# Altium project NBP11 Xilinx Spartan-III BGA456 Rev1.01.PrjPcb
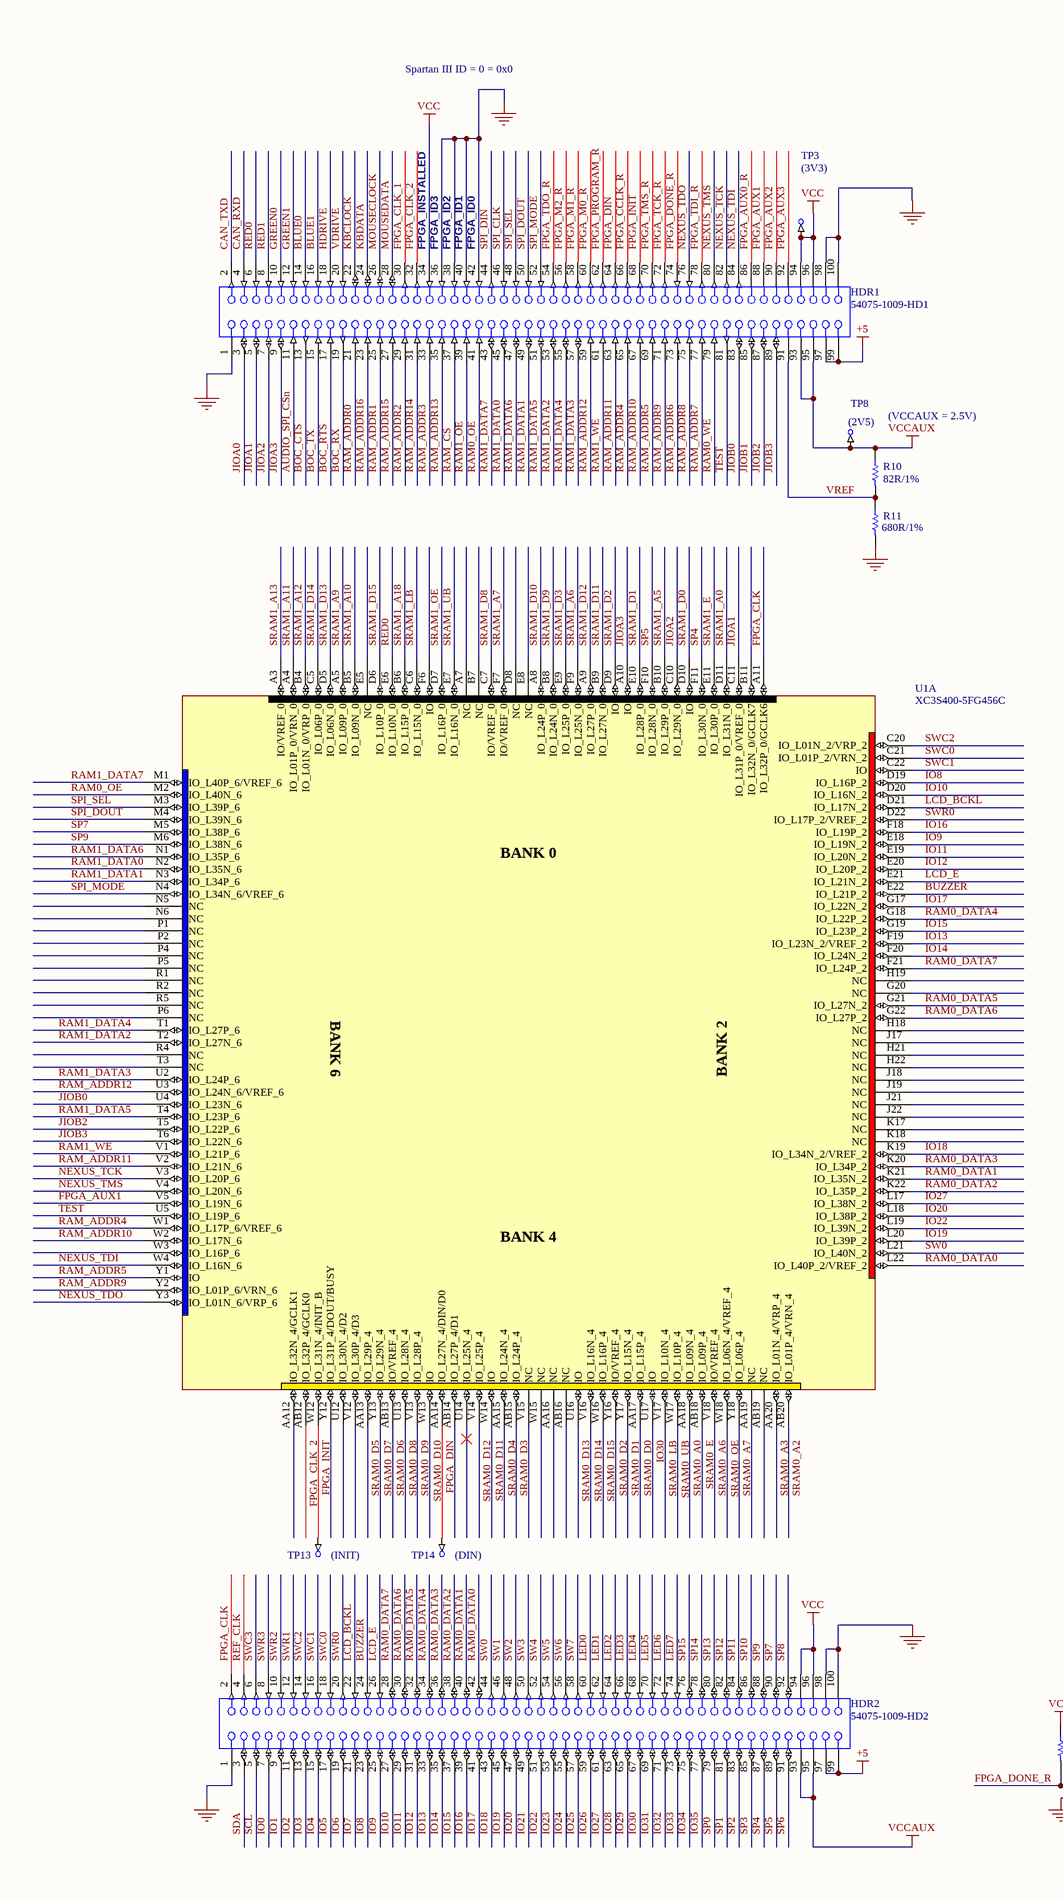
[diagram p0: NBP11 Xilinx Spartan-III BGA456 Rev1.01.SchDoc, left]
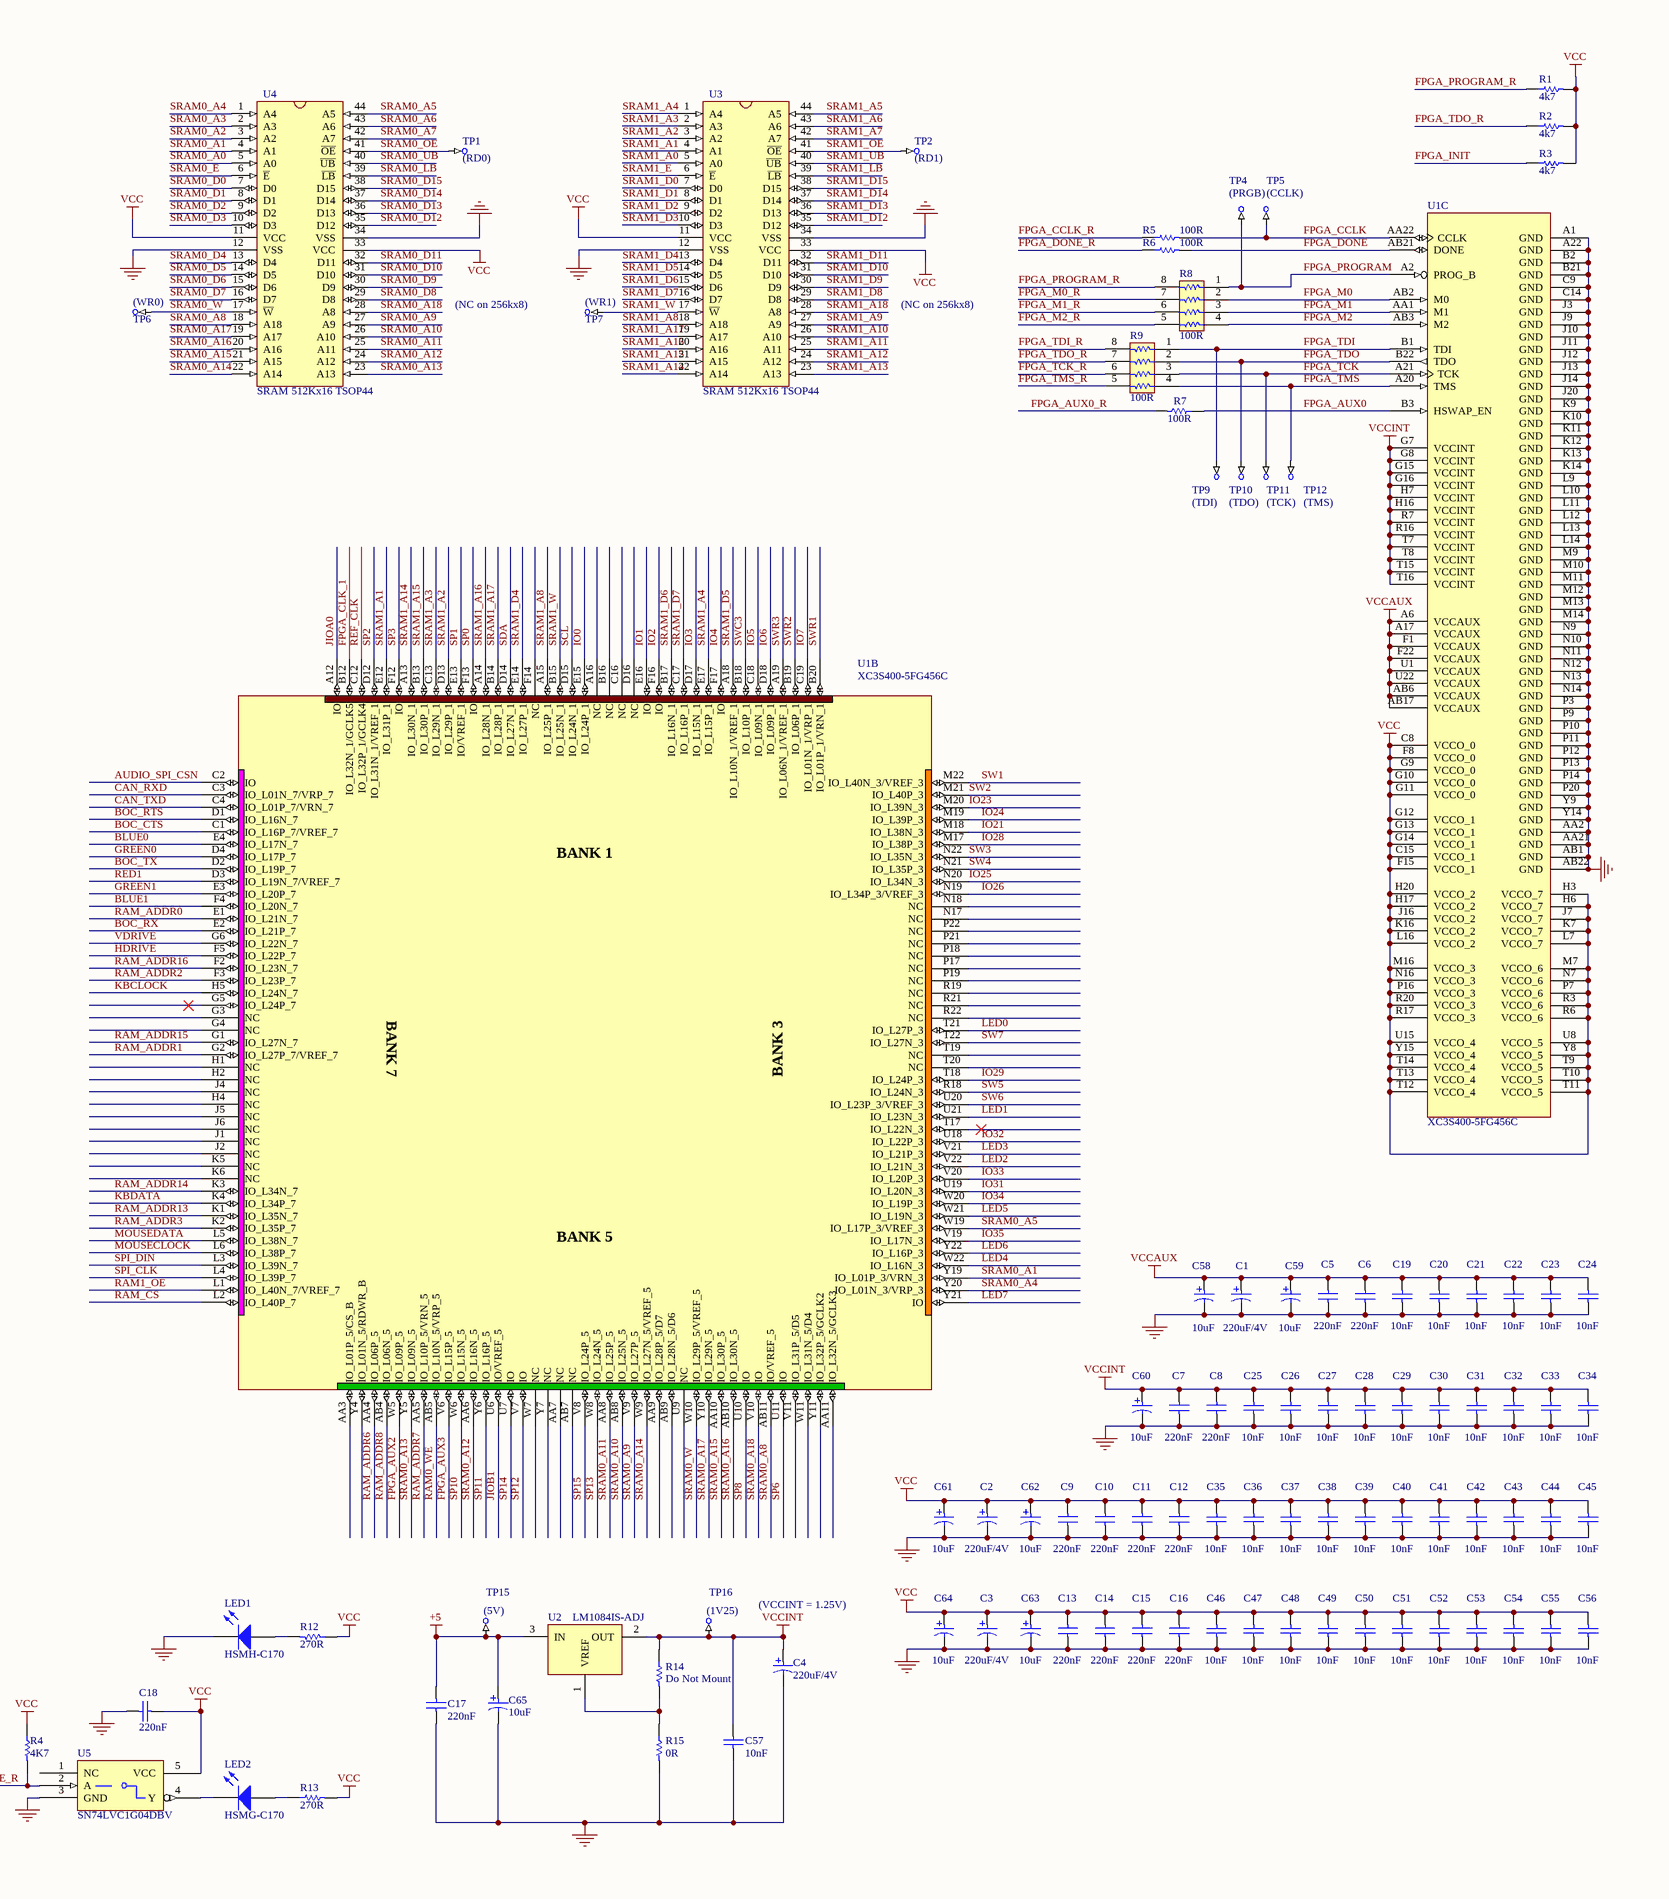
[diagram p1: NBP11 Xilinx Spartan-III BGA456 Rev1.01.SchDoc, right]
1 sheet, 105 parts. Net scope: global (net labels, ports and power ports of the same name join across sheets).
Board file: NBP11 Xilinx Spartan-III BGA456 Rev1.01.PcbDoc

## Sheet NBP11 Xilinx Spartan-III BGA456 Rev1.01.SchDoc: Spartan III BGA456 Daughterboard
size A2; Author: Ch.W.; Organization: Altium Limited; Address1: L3, 12a Rodborough Rd; Address2: Frenchs Forest; Address3: NSW; Address4: Australia 2086; DocumentNumber: 1; Revision: 1.01; SheetNumber: 1; SheetTotal: 1

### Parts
C1  220uF/4V  [MCCT-D]
C2  220uF/4V  [MCCT-D]
C3  220uF/4V  [MCCT-D]
C4  220uF/4V  [MCCT-D]
C5  220nF  [CC1608-0603]
C6  220nF  [CC1608-0603]
C7  220nF  [CC1608-0603]
C8  220nF  [CC1608-0603]
C9  220nF  [CC1608-0603]
C10  220nF  [CC1608-0603]
C11  220nF  [CC1608-0603]
C12  220nF  [CC1608-0603]
C13  220nF  [CC1608-0603]
C14  220nF  [CC1608-0603]
C15  220nF  [CC1608-0603]
C16  220nF  [CC1608-0603]
C17  220nF  [CC1608-0603]
C18  220nF  [CC1608-0603]
C19  10nF  [CC1608-0603]
C20  10nF  [CC1608-0603]
C21  10nF  [CC1608-0603]
C22  10nF  [CC1608-0603]
C23  10nF  [CC1608-0603]
C24  10nF  [CC1608-0603]
C25  10nF  [CC1608-0603]
C26  10nF  [CC1608-0603]
C27  10nF  [CC1608-0603]
C28  10nF  [CC1608-0603]
C29  10nF  [CC1608-0603]
C30  10nF  [CC1608-0603]
C31  10nF  [CC1608-0603]
C32  10nF  [CC1608-0603]
C33  10nF  [CC1608-0603]
C34  10nF  [CC1608-0603]
C35  10nF  [CC1608-0603]
C36  10nF  [CC1608-0603]
C37  10nF  [CC1608-0603]
C38  10nF  [CC1608-0603]
C39  10nF  [CC1608-0603]
C40  10nF  [CC1608-0603]
C41  10nF  [CC1608-0603]
C42  10nF  [CC1608-0603]
C43  10nF  [CC1608-0603]
C44  10nF  [CC1608-0603]
C45  10nF  [CC1608-0603]
C46  10nF  [CC1608-0603]
C47  10nF  [CC1608-0603]
C48  10nF  [CC1608-0603]
C49  10nF  [CC1608-0603]
C50  10nF  [CC1608-0603]
C51  10nF  [CC1608-0603]
C52  10nF  [CC1608-0603]
C53  10nF  [CC1608-0603]
C54  10nF  [CC1608-0603]
C55  10nF  [CC1608-0603]
C56  10nF  [CC1608-0603]
C57  10nF  [CC1608-0603]
C58  10uF  [MCCT-B]
C59  10uF  [MCCT-B]
C60  10uF  [MCCT-B]
C61  10uF  [MCCT-B]
C62  10uF  [MCCT-B]
C63  10uF  [MCCT-B]
C64  10uF  [MCCT-B]
C65  10uF  [MCCT-B]
HDR1  54075-1009-HD1  [54075]
HDR2  54075-1009-HD2  [54075]
LED1  HSMH-C170  [SMD _LED]
LED2  HSMG-C170  [SMD _LED]
R1  4k7  [CR2012-0805]
R2  4k7  [CR2012-0805]
R3  4k7  [CR2012-0805]
R4  4K7  [CR2012-0805]
R5  100R  [CR2012-0805]
R6  100R  [CR2012-0805]
R7  100R  [CR2012-0805]
R8  100R  [MNR34]
R9  100R  [MNR34]
R10  82R/1%  [CR2012-0805]
R11  680R/1%  [CR2012-0805]
R12  270R  [CR2012-0805]
R13  270R  [CR2012-0805]
R14  Do Not Mount  [CR2012-0805]
R15  0R  [CR2012-0805]
TP1  (RD0)  [TestPin]  (no BOM)
TP2  (RD1)  [TestPin]  (no BOM)
TP3  (3V3)  [TestPin]  (no BOM)
TP4  (PRGB)  [TestPin]  (no BOM)
TP5  (CCLK)  [TestPin]  (no BOM)
TP6  (WR0)  [TestPin]  (no BOM)
TP7  (WR1)  [TestPin]  (no BOM)
TP8  (2V5)  [TestPin]  (no BOM)
TP9  (TDI)  [TestPin]  (no BOM)
TP10  (TDO)  [TestPin]  (no BOM)
TP11  (TCK)  [TestPin]  (no BOM)
TP12  (TMS)  [TestPin]  (no BOM)
TP13  (INIT)  [TestPin]  (no BOM)
TP14  (DIN)  [TestPin]  (no BOM)
TP15  (5V)  [TestPin]  (no BOM)
TP16  (1V25)  [TestPin]  (no BOM)
U1  XC3S400-5FG456C  [FG456]  (parts A,B,C of 3)
U2  LM1084IS-ADJ  [TO-263]
U3  SRAM 512Kx16 TSOP44  [SO-G44/P.8]
U4  SRAM 512Kx16 TSOP44  [SO-G44/P.8]
U5  SN74LVC1G04DBV  [SO-G5/P.95]

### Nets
+5: C17.1 C65.1 HDR1.97 HDR1.99 HDR2.97 HDR2.99 TP15.1 U2.3(IN)
GND: C1.2 C2.2 C3.2 C4.2 C5.2 C6.2 C7.2 C8.2 C9.2 C10.2 C11.2 C12.2 C13.2 C14.2 C15.2 C16.2 C17.2 C18.1 C19.2 C20.2 C21.2 C22.2 C23.2 C24.2 C25.2 C26.2 C27.2 C28.2 C29.2 C30.2 C31.2 C32.2 C33.2 C34.2 C35.2 C36.2 C37.2 C38.2 C39.2 C40.2 C41.2 C42.2 C43.2 C44.2 C45.2 C46.2 C47.2 C48.2 C49.2 C50.2 C51.2 C52.2 C53.2 C54.2 C55.2 C56.2 C57.2 C58.2 C59.2 C60.2 C61.2 C62.2 C63.2 C64.2 C65.2 HDR1.1 HDR1.36 HDR1.38 HDR1.40 HDR1.42 HDR1.98 HDR1.100 HDR2.1 HDR2.98 HDR2.100 LED1.2(K) R11.2 R15.2 U1.A1(GND) U1.A22(GND) U1.AA2(GND) U1.AA21(GND) U1.AB1(GND) U1.AB22(GND) U1.B2(GND) U1.B21(GND) U1.C9(GND) U1.C14(GND) U1.J3(GND) U1.J9(GND) U1.J10(GND) U1.J11(GND) U1.J12(GND) U1.J13(GND) U1.J14(GND) U1.J20(GND) U1.K9(GND) U1.K10(GND) U1.K11(GND) U1.K12(GND) U1.K13(GND) U1.K14(GND) U1.L9(GND) U1.L10(GND) U1.L11(GND) U1.L12(GND) U1.L13(GND) U1.L14(GND) U1.M9(GND) U1.M10(GND) U1.M11(GND) U1.M12(GND) U1.M13(GND) U1.M14(GND) U1.N9(GND) U1.N10(GND) U1.N11(GND) U1.N12(GND) U1.N13(GND) U1.N14(GND) U1.P3(GND) U1.P9(GND) U1.P10(GND) U1.P11(GND) U1.P12(GND) U1.P13(GND) U1.P14(GND) U1.P20(GND) U1.Y9(GND) U1.Y14(GND) U3.12(VSS) U3.34(VSS) U4.12(VSS) U4.34(VSS) U5.3(GND)
VCC: C2.1 C3.1 C9.1 C10.1 C11.1 C12.1 C13.1 C14.1 C15.1 C16.1 C18.2 C35.1 C36.1 C37.1 C38.1 C39.1 C40.1 C41.1 C42.1 C43.1 C44.1 C45.1 C46.1 C47.1 C48.1 C49.1 C50.1 C51.1 C52.1 C53.1 C54.1 C55.1 C56.1 C61.1 C62.1 C63.1 C64.1 HDR1.34 HDR1.94 HDR1.96 HDR2.94 HDR2.96 R1.2 R2.2 R3.2 R4.1 R12.1 R13.2 TP3.1 U1.C8(VCCO_0) U1.C15(VCCO_1) U1.F8(VCCO_0) U1.F15(VCCO_1) U1.G9(VCCO_0) U1.G10(VCCO_0) U1.G11(VCCO_0) U1.G12(VCCO_1) U1.G13(VCCO_1) U1.G14(VCCO_1) U1.H3(VCCO_7) U1.H6(VCCO_7) U1.H17(VCCO_2) U1.H20(VCCO_2) U1.J7(VCCO_7) U1.J16(VCCO_2) U1.K7(VCCO_7) U1.K16(VCCO_2) U1.L7(VCCO_7) U1.L16(VCCO_2) U1.M7(VCCO_6) U1.M16(VCCO_3) U1.N7(VCCO_6) U1.N16(VCCO_3) U1.P7(VCCO_6) U1.P16(VCCO_3) U1.R3(VCCO_6) U1.R6(VCCO_6) U1.R17(VCCO_3) U1.R20(VCCO_3) U1.T9(VCCO_5) U1.T10(VCCO_5) U1.T11(VCCO_5) U1.T12(VCCO_4) U1.T13(VCCO_4) U1.T14(VCCO_4) U1.U8(VCCO_5) U1.U15(VCCO_4) U1.Y8(VCCO_5) U1.Y15(VCCO_4) U3.11(VCC) U3.33(VCC) U4.11(VCC) U4.33(VCC) U5.5(VCC)
VCCAUX: C1.1 C5.1 C6.1 C19.1 C20.1 C21.1 C22.1 C23.1 C24.1 C58.1 C59.1 HDR1.93 HDR1.95 HDR2.93 HDR2.95 R10.1 TP8.1 U1.A6(VCCAUX) U1.A17(VCCAUX) U1.AB6(VCCAUX) U1.AB17(VCCAUX) U1.F1(VCCAUX) U1.F22(VCCAUX) U1.U1(VCCAUX) U1.U22(VCCAUX)
VCCINT: C4.1 C7.1 C8.1 C25.1 C26.1 C27.1 C28.1 C29.1 C30.1 C31.1 C32.1 C33.1 C34.1 C57.1 C60.1 R14.1 TP16.1 U1.G7(VCCINT) U1.G8(VCCINT) U1.G15(VCCINT) U1.G16(VCCINT) U1.H7(VCCINT) U1.H16(VCCINT) U1.R7(VCCINT) U1.R16(VCCINT) U1.T7(VCCINT) U1.T8(VCCINT) U1.T15(VCCINT) U1.T16(VCCINT) U2.2(OUT)
AUDIO_SPI_CSn: HDR1.11 U1.C2(IO)
BLUE0: HDR1.14 U1.E4(IO_L17N_7)
BLUE1: HDR1.16 U1.F4(IO_L20N_7)
BOC_CTS: HDR1.13 U1.C1(IO_L16P_7/VREF_7)
BOC_RTS: HDR1.17 U1.D1(IO_L16N_7)
BOC_RX: HDR1.19 U1.E2(IO_L21P_7)
BOC_TX: HDR1.15 U1.D2(IO_L19P_7)
BUZZER: HDR2.24 U1.E22(IO_L21P_2)
CAN_RXD: HDR1.4 U1.C3(IO_L01N_7/VRP_7)
CAN_TXD: HDR1.2 U1.C4(IO_L01P_7/VRN_7)
FPGA_AUX0: R7.1 U1.B3(HSWAP_EN)
FPGA_AUX0_R: HDR1.86 R7.2
FPGA_AUX1: HDR1.88 U1.V5(IO_L19N_6)
FPGA_AUX2: HDR1.90 U1.W5(IO_L09P_5)
FPGA_AUX3: HDR1.92 U1.V6(IO_L15P_5)
FPGA_CCLK: R5.2 TP5.1 U1.AA22(CCLK)
FPGA_CCLK_R: HDR1.66 R5.1
FPGA_CLK: HDR2.2 U1.A11(IO_L32P_0/GCLK6)
FPGA_CLK_1: HDR1.30 U1.B12(IO_L32N_1/GCLK5)
FPGA_CLK_2: HDR1.32 U1.AB12(IO_L32P_4/GCLK0)
FPGA_DIN: HDR1.64 TP14.1 U1.AA14(IO_L27N_4/DIN/D0)
FPGA_DONE: R6.2 U1.AB21(DONE)
FPGA_DONE_R: HDR1.74 R4.2 R6.1 U5.2(A)
FPGA_INIT: HDR1.68 R3.1 TP13.1 U1.W12(IO_L31N_4/INIT_B)
FPGA_M0: R8.2 U1.AB2(M0)
FPGA_M0_R: HDR1.60 R8.7
FPGA_M1: R8.3 U1.AA1(M1)
FPGA_M1_R: HDR1.58 R8.6
FPGA_M2: R8.4 U1.AB3(M2)
FPGA_M2_R: HDR1.56 R8.5
FPGA_PROGRAM: R8.1 TP4.1 U1.A2(PROG_B)
FPGA_PROGRAM_R: HDR1.62 R1.1 R8.8
FPGA_TCK: R9.3 TP11.1 U1.A21(TCK)
FPGA_TCK_R: HDR1.72 R9.6
FPGA_TDI: R9.1 TP9.1 U1.B1(TDI)
FPGA_TDI_R: HDR1.78 R9.8
FPGA_TDO: R9.2 TP10.1 U1.B22(TDO)
FPGA_TDO_R: HDR1.54 R2.1 R9.7
FPGA_TMS: R9.4 TP12.1 U1.A20(TMS)
FPGA_TMS_R: HDR1.70 R9.5
GREEN0: HDR1.10 U1.D4(IO_L17P_7)
GREEN1: HDR1.12 U1.E3(IO_L20P_7)
HDRIVE: HDR1.18 U1.F5(IO_L22P_7)
IO0: HDR2.7 U1.E15(IO_L24P_1)
IO1: HDR2.9 U1.E16(IO)
IO2: HDR2.11 U1.F16(IO)
IO3: HDR2.13 U1.D17(IO_L15N_1)
IO4: HDR2.15 U1.F17(IO)
IO5: HDR2.17 U1.C18(IO_L09N_1)
IO6: HDR2.19 U1.D18(IO_L09P_1)
IO7: HDR2.21 U1.C19(IO_L01N_1/VRP_1)
IO8: HDR2.23 U1.D19(IO_L16P_2)
IO9: HDR2.25 U1.E18(IO_L19N_2)
IO10: HDR2.27 U1.D20(IO_L16N_2)
IO11: HDR2.29 U1.E19(IO_L20N_2)
IO12: HDR2.31 U1.E20(IO_L20P_2)
IO13: HDR2.33 U1.F19(IO_L23N_2/VREF_2)
IO14: HDR2.35 U1.F20(IO_L24N_2)
IO15: HDR2.37 U1.G19(IO_L23P_2)
IO16: HDR2.39 U1.F18(IO_L19P_2)
IO17: HDR2.41 U1.G17(IO_L22N_2)
IO18: HDR2.43 U1.K19(IO_L34N_2/VREF_2)
IO19: HDR2.45 U1.L20(IO_L39P_2)
IO20: HDR2.47 U1.L18(IO_L38P_2)
IO21: HDR2.49 U1.M18(IO_L38N_3)
IO22: HDR2.51 U1.L19(IO_L39N_2)
IO23: HDR2.53 U1.M20(IO_L39N_3)
IO24: HDR2.55 U1.M19(IO_L39P_3)
IO25: HDR2.57 U1.N20(IO_L34N_3)
IO26: HDR2.59 U1.N19(IO_L34P_3/VREF_3)
IO27: HDR2.61 U1.L17(IO_L38N_2)
IO28: HDR2.63 U1.M17(IO_L38P_3)
IO29: HDR2.65 U1.T18(IO_L24P_3)
IO30: HDR2.67 U1.U17(IO)
IO31: HDR2.69 U1.U19(IO_L20N_3)
IO32: HDR2.71 U1.U18(IO_L22P_3)
IO33: HDR2.73 U1.V20(IO_L20P_3)
IO34: HDR2.75 U1.W20(IO_L19P_3)
IO35: HDR2.77 U1.V19(IO_L17N_3)
JIOA0: HDR1.3 U1.A12(IO)
JIOA1: HDR1.5 U1.C11(IO_L31P_0/VREF_0)
JIOA2: HDR1.7 U1.C10(IO_L29N_0)
JIOA3: HDR1.9 U1.A10(IO)
JIOB0: HDR1.83 U1.U4(IO_L23N_6)
JIOB1: HDR1.85 U1.U6(IO/VREF_5)
JIOB2: HDR1.87 U1.T5(IO_L22P_6)
JIOB3: HDR1.89 U1.T6(IO_L22N_6)
KBCLOCK: HDR1.22 U1.H5(IO_L24N_7)
KBDATA: HDR1.24 U1.K4(IO_L34P_7)
LCD_BCKL: HDR2.22 U1.D21(IO_L17N_2)
LCD_E: HDR2.26 U1.E21(IO_L21N_2)
LED0: HDR2.60 U1.T21(IO_L27P_3)
LED1: HDR2.62 U1.U21(IO_L23N_3)
LED2: HDR2.64 U1.V22(IO_L21N_3)
LED3: HDR2.66 U1.V21(IO_L21P_3)
LED4: HDR2.68 U1.W22(IO_L16N_3)
LED5: HDR2.70 U1.W21(IO_L19N_3)
LED6: HDR2.72 U1.Y22(IO_L16P_3)
LED7: HDR2.74 U1.Y21(IO)
MOUSECLOCK: HDR1.26 U1.L6(IO_L38P_7)
MOUSEDATA: HDR1.28 U1.L5(IO_L38N_7)
NEXUS_TCK: HDR1.82 U1.V3(IO_L20P_6)
NEXUS_TDI: HDR1.84 U1.W4(IO_L16N_6)
NEXUS_TDO: HDR1.76 U1.Y3(IO_L01N_6/VRP_6)
NEXUS_TMS: HDR1.80 U1.V4(IO_L20N_6)
RAM0_DATA0: HDR2.42 U1.L22(IO_L40P_2/VREF_2)
RAM0_DATA1: HDR2.40 U1.K21(IO_L35N_2)
RAM0_DATA2: HDR2.38 U1.K22(IO_L35P_2)
RAM0_DATA3: HDR2.36 U1.K20(IO_L34P_2)
RAM0_DATA4: HDR2.34 U1.G18(IO_L22P_2)
RAM0_DATA5: HDR2.32 U1.G21(IO_L27N_2)
RAM0_DATA6: HDR2.30 U1.G22(IO_L27P_2)
RAM0_DATA7: HDR2.28 U1.F21(IO_L24P_2)
RAM0_OE: HDR1.41 U1.M2(IO_L40N_6)
RAM0_WE: HDR1.79 U1.AB5(IO_L10N_5/VRP_5)
RAM1_DATA0: HDR1.45 U1.N2(IO_L35N_6)
RAM1_DATA1: HDR1.49 U1.N3(IO_L34P_6)
RAM1_DATA2: HDR1.53 U1.T2(IO_L27N_6)
RAM1_DATA3: HDR1.57 U1.U2(IO_L24P_6)
RAM1_DATA4: HDR1.55 U1.T1(IO_L27P_6)
RAM1_DATA5: HDR1.51 U1.T4(IO_L23P_6)
RAM1_DATA6: HDR1.47 U1.N1(IO_L35P_6)
RAM1_DATA7: HDR1.43 U1.M1(IO_L40P_6/VREF_6)
RAM1_OE: HDR1.39 U1.L1(IO_L40N_7/VREF_7)
RAM1_WE: HDR1.61 U1.V1(IO_L21P_6)
RAM_ADDR0: HDR1.21 U1.E1(IO_L21N_7)
RAM_ADDR1: HDR1.25 U1.G2(IO_L27P_7/VREF_7)
RAM_ADDR2: HDR1.29 U1.F3(IO_L23P_7)
RAM_ADDR3: HDR1.33 U1.K2(IO_L35P_7)
RAM_ADDR4: HDR1.65 U1.W1(IO_L17P_6/VREF_6)
RAM_ADDR5: HDR1.69 U1.Y1(IO)
RAM_ADDR6: HDR1.73 U1.AA4(IO_L06P_5)
RAM_ADDR7: HDR1.77 U1.AA5(IO_L10P_5/VRN_5)
RAM_ADDR8: HDR1.75 U1.AB4(IO_L06N_5)
RAM_ADDR9: HDR1.71 U1.Y2(IO_L01P_6/VRN_6)
RAM_ADDR10: HDR1.67 U1.W2(IO_L17N_6)
RAM_ADDR11: HDR1.63 U1.V2(IO_L21N_6)
RAM_ADDR12: HDR1.59 U1.U3(IO_L24N_6/VREF_6)
RAM_ADDR13: HDR1.35 U1.K1(IO_L35N_7)
RAM_ADDR14: HDR1.31 U1.K3(IO_L34N_7)
RAM_ADDR15: HDR1.27 U1.G1(IO_L27N_7)
RAM_ADDR16: HDR1.23 U1.F2(IO_L23N_7)
RAM_CS: HDR1.37 U1.L2(IO_L40P_7)
RED0: HDR1.6 U1.E6(IO_L10N_0)
RED1: HDR1.8 U1.D3(IO_L19N_7/VREF_7)
REF_CLK: HDR2.4 U1.C12(IO_L32P_1/GCLK4)
SCL: HDR2.5 U1.D15(IO_L24N_1)
SDA: HDR2.3 U1.D14(IO_L27N_1)
SP0: HDR2.79 U1.F13(IO)
SP1: HDR2.81 U1.E13(IO/VREF_1)
SP2: HDR2.83 U1.D12(IO_L31N_1/VREF_1)
SP3: HDR2.85 U1.F12(IO)
SP4: HDR2.87 U1.F11(IO_L30N_0)
SP5: HDR2.89 U1.F10(IO_L28N_0)
SP6: HDR2.91 U1.U11(IO)
SP7: HDR2.90 U1.M5(IO_L38P_6)
SP8: HDR2.92 U1.U10(IO)
SP9: HDR2.88 U1.M6(IO_L38N_6)
SP10: HDR2.86 U1.W6(IO_L15N_5)
SP11: HDR2.84 U1.Y6(IO_L16P_5)
SP12: HDR2.82 U1.V7(IO)
SP13: HDR2.80 U1.W8(IO_L24N_5)
SP14: HDR2.78 U1.U7(IO)
SP15: HDR2.76 U1.V8(IO_L24P_5)
SPI_CLK: HDR1.46 U1.L4(IO_L39P_7)
SPI_DIN: HDR1.44 U1.L3(IO_L39N_7)
SPI_DOUT: HDR1.50 U1.M4(IO_L39N_6)
SPI_MODE: HDR1.52 U1.N4(IO_L34N_6/VREF_6)
SPI_SEL: HDR1.48 U1.M3(IO_L39P_6)
SRAM0_A0: U1.AA18(IO_L09N_4) U3.5(A0)
SRAM0_A1: U1.Y19(IO_L01P_3/VRN_3) U3.4(A1)
SRAM0_A2: U1.AB20(IO_L01P_4/VRN_4) U3.3(A2)
SRAM0_A3: U1.AA20(IO_L01N_4/VRP_4) U3.2(A3)
SRAM0_A4: U1.Y20(IO_L01N_3/VRP_3) U3.1(A4)
SRAM0_A5: U1.W19(IO_L17P_3/VREF_3) U3.44(A5)
SRAM0_A6: U1.V18(IO/VREF_4) U3.43(A6)
SRAM0_A7: U1.Y18(IO_L06P_4) U3.42(A7)
SRAM0_A8: U1.AB11(IO/VREF_5) U3.18(A18)
SRAM0_A9: U1.V9(IO_L27P_5) U3.27(A9)
SRAM0_A10: U1.AB8(IO_L25N_5) U3.26(A10)
SRAM0_A11: U1.AA8(IO_L25P_5) U3.25(A11)
SRAM0_A12: U1.AA6(IO_L16N_5) U3.24(A12)
SRAM0_A13: U1.Y5(IO_L09N_5) U3.23(A13)
SRAM0_A14: U1.W9(IO_L27N_5/VREF_5) U3.22(A14)
SRAM0_A15: U1.AA10(IO_L30P_5) U3.21(A15)
SRAM0_A16: U1.AB10(IO_L30N_5) U3.20(A16)
SRAM0_A17: U1.Y10(IO_L29N_5) U3.19(A17)
SRAM0_A18: U1.V10(IO) U3.28(A8)
SRAM0_D0: U1.AA17(IO_L15P_4) U3.7(D0)
SRAM0_D1: U1.Y17(IO_L15N_4) U3.8(D1)
SRAM0_D2: U1.Y16(IO/VREF_4) U3.9(D2)
SRAM0_D3: U1.AB15(IO_L24P_4) U3.10(D3)
SRAM0_D4: U1.AA15(IO_L24N_4) U3.13(D4)
SRAM0_D5: U1.AA13(IO_L29P_4) U3.14(D5)
SRAM0_D6: U1.AB13(IO/VREF_4) U3.15(D6)
SRAM0_D7: U1.Y13(IO_L29N_4) U3.16(D7)
SRAM0_D8: U1.U13(IO_L28N_4) U3.29(D8)
SRAM0_D9: U1.V13(IO_L28P_4) U3.30(D9)
SRAM0_D10: U1.W13(IO) U3.31(D10)
SRAM0_D11: U1.W14(IO) U3.32(D11)
SRAM0_D12: U1.V14(IO_L25P_4) U3.35(D12)
SRAM0_D13: U1.U16(IO) U3.36(D13)
SRAM0_D14: U1.V16(IO_L16N_4) U3.37(D14)
SRAM0_D15: U1.W16(IO_L16P_4) U3.38(D15)
SRAM0_E: U1.AB18(IO_L09P_4) U3.6(~{E})
SRAM0_LB: U1.V17(IO_L10N_4) U3.39(~{LB})
SRAM0_OE: TP1.1 U1.W18(IO_L06N_4/VREF_4) U3.41(~{OE})
SRAM0_UB: U1.W17(IO_L10P_4) U3.40(~{UB})
SRAM0_W: TP6.1 U1.W10(IO_L29P_5/VREF_5) U3.17(~{W})
SRAM1_A0: U1.D11(IO_L31N_0) U4.5(A0)
SRAM1_A1: U1.E12(IO_L31P_1) U4.4(A1)
SRAM1_A2: U1.D13(IO_L29P_1) U4.3(A2)
SRAM1_A3: U1.C13(IO_L29N_1) U4.2(A3)
SRAM1_A4: U1.E17(IO_L15P_1) U4.1(A4)
SRAM1_A5: U1.B10(IO_L29P_0) U4.44(A5)
SRAM1_A6: U1.F9(IO_L25N_0) U4.43(A6)
SRAM1_A7: U1.F7(IO/VREF_0) U4.42(A7)
SRAM1_A8: U1.A15(IO_L25P_1) U4.18(A18)
SRAM1_A9: U1.A5(IO_L09P_0) U4.27(A9)
SRAM1_A10: U1.B5(IO_L09N_0) U4.26(A10)
SRAM1_A11: U1.A4(IO_L01P_0/VRN_0) U4.25(A11)
SRAM1_A12: U1.B4(IO_L01N_0/VRP_0) U4.24(A12)
SRAM1_A13: U1.A3(IO/VREF_0) U4.23(A13)
SRAM1_A14: U1.A13(IO_L30N_1) U4.22(A14)
SRAM1_A15: U1.B13(IO_L30P_1) U4.21(A15)
SRAM1_A16: U1.A14(IO_L28N_1) U4.20(A16)
SRAM1_A17: U1.B14(IO_L28P_1) U4.19(A17)
SRAM1_A18: U1.B6(IO_L15P_0) U4.28(A8)
SRAM1_D0: U1.D10(IO) U4.7(D0)
SRAM1_D1: U1.E10(IO_L28P_0) U4.8(D1)
SRAM1_D2: U1.D9(IO) U4.9(D2)
SRAM1_D3: U1.E9(IO_L25P_0) U4.10(D3)
SRAM1_D4: U1.E14(IO_L27P_1) U4.13(D4)
SRAM1_D5: U1.A18(IO_L10N_1/VREF_1) U4.14(D5)
SRAM1_D6: U1.B17(IO_L16N_1) U4.15(D6)
SRAM1_D7: U1.C17(IO_L16P_1) U4.16(D7)
SRAM1_D8: U1.C7(IO/VREF_0) U4.29(D8)
SRAM1_D9: U1.B8(IO_L24N_0) U4.30(D9)
SRAM1_D10: U1.A8(IO_L24P_0) U4.31(D10)
SRAM1_D11: U1.B9(IO_L27N_0) U4.32(D11)
SRAM1_D12: U1.A9(IO_L27P_0) U4.35(D12)
SRAM1_D13: U1.D5(IO_L06N_0) U4.36(D13)
SRAM1_D14: U1.C5(IO_L06P_0) U4.37(D14)
SRAM1_D15: U1.D6(IO_L10P_0) U4.38(D15)
SRAM1_E: U1.E11(IO_L30P_0) U4.6(~{E})
SRAM1_LB: U1.C6(IO_L15N_0) U4.39(~{LB})
SRAM1_OE: TP2.1 U1.D7(IO_L16P_0) U4.41(~{OE})
SRAM1_UB: U1.E7(IO_L16N_0) U4.40(~{UB})
SRAM1_W: TP7.1 U1.B15(IO_L25N_1) U4.17(~{W})
SW0: HDR2.44 U1.L21(IO_L40N_2)
SW1: HDR2.46 U1.M22(IO_L40N_3/VREF_3)
SW2: HDR2.48 U1.M21(IO_L40P_3)
SW3: HDR2.50 U1.N22(IO_L35N_3)
SW4: HDR2.52 U1.N21(IO_L35P_3)
SW5: HDR2.54 U1.R18(IO_L24N_3)
SW6: HDR2.56 U1.U20(IO_L23P_3/VREF_3)
SW7: HDR2.58 U1.T22(IO_L27N_3)
SWC0: HDR2.18 U1.C21(IO_L01P_2/VRN_2)
SWC1: HDR2.16 U1.C22(IO)
SWC2: HDR2.14 U1.C20(IO_L01N_2/VRP_2)
SWC3: HDR2.6 U1.B18(IO_L10P_1)
SWR0: HDR2.20 U1.D22(IO_L17P_2/VREF_2)
SWR1: HDR2.12 U1.B20(IO_L01P_1/VRN_1)
SWR2: HDR2.10 U1.B19(IO_L06P_1)
SWR3: HDR2.8 U1.A19(IO_L06N_1/VREF_1)
TEST: HDR1.81 U1.U5(IO_L19P_6)
VDRIVE: HDR1.20 U1.G6(IO_L22N_7)
VREF: HDR1.91 R10.2 R11.1
NetLED1_1: LED1.1(A) R12.2
NetLED2_1: LED2.1(A) R13.1
NetLED2_2: LED2.2(K) U5.4(Y)
NetR14_2: R14.2 R15.1 U2.1(VREF)

Not connected (* = marked no-connect by the designer): U1 A7(NC) A16(NC) AA3(IO_L01P_5/CS_B) AA7(NC) AA9(IO_L28P_5/D7) AA11(IO_L32N_5/GCLK3) AA12(IO_L32N_4/GCLK1) AA16(NC) AA19(NC) AB7(NC) AB9(IO_L28N_5/D6) AB14(IO_L27P_4/D1) AB16(NC) AB19(NC) B7(NC) B11(IO_L32N_0/GCLK7) B16(NC) C16(NC) D8(NC) D16(NC) E5(NC) E8(NC) F6(IO) F14(NC) G3(NC) G4(NC) G5(IO_L24P_7)* G20(NC) H1(NC) H2(NC) H4(NC) H18(NC) H19(NC) H21(NC) H22(NC) J1(NC) J2(NC) J4(NC) J5(NC) J6(NC) J17(NC) J18(NC) J19(NC) J21(NC) J22(NC) K5(NC) K6(NC) K17(NC) K18(NC) N5(NC) N6(NC) N17(NC) N18(NC) P1(NC) P2(NC) P4(NC) P5(NC) P6(NC) P17(NC) P18(NC) P19(NC) P21(NC) P22(NC) R1(NC) R2(NC) R4(NC) R5(NC) R19(NC) R21(NC) R22(NC) T3(NC) T17(IO_L22N_3)* T19(NC) T20(NC) U9(NC) U12(IO_L30N_4/D2) U14(IO_L25N_4)* V11(IO_L31P_5/D5) V12(IO_L30P_4/D3) V15(NC) W3(IO_L16P_6) W7(NC) W11(IO_L31N_5/D4) W15(NC) Y4(IO_L01N_5/RDWR_B) Y7(NC) Y11(IO_L32P_5/GCLK2) Y12(IO_L31P_4/DOUT/BUSY); U5 1(NC)

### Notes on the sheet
- Spartan III ID = 0 = 0x0
- (near HDR1) FPGA_INSTALLED
- (near HDR1) FPGA_ID3
- (near HDR1) FPGA_ID2
- (near HDR1) FPGA_ID1
- (near HDR1) FPGA_ID0
- (NC on 256kx8)
- (VCCAUX = 2.5V)
- (VCCINT = 1.25V)

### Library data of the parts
C1-C4 C58-C65 = CAP_POLAR: Polar Capacitor
C5-C57 = CAP: Capacitor
HDR1 = 54075-1009-HD1: Board-to-Board, Docking Station, 0.80mm (.031") Pitch, Shielded Receptacle, Vertical, Ultra Low Profile, SMT; Manufacturer: Molex; Package Information: Latest Revision: Jun-2001; Mating Height: 8.5mm; Voltage: 100V; Current: 0.5A; Contact Resistance: 40mOhm max; PCB Layout: Complies with Manufacturer's Recommendation.
HDR2 = 54075-1009-HD2: Board-to-Board, Docking Station, 0.80mm (.031") Pitch, Shielded Receptacle, Vertical, Ultra Low Profile, SMT; Manufacturer: Molex; Package Information: Latest Revision: Jun-2001; Mating Height: 8.5mm; Voltage: 100V; Current: 0.5A; Contact Resistance: 40mOhm max; PCB Layout: Complies with Manufacturer's Recommendation.
LED1 LED2 = HSMX-C670: Typical RED GaAs SMD LED Agilent make; Manufacturer: Generic Components; Class I: Optoelectronic; Fitted: True
R1-R7 R10-R15 = RES: Resistor
R8 R9 = MNR34: 3216x4 Resistor Array
TP1-TP16 = TestPin
U1 = XC3S400-5FG456C: Spartan-3 1.2V FPGA, 264 User I/Os, 456-ball FBGA, High Performance, Commercial Grade; Package Information: Latest Revision: ver1.1, Apr-2001; Code - JEDEC: MO-151-AAJ-1
U2 = LM1084IS-ADJ: 5A Low Dropout Possitive Regulators
U3 U4 = SRAM 512Kx16 TSOP44: 512Kx16Bit SRAM TSOP44
U5 = SN74AHC1G04DBVR: Manufacturer: TI; Fitted: True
